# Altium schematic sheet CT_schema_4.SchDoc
size 193 x 163 mm
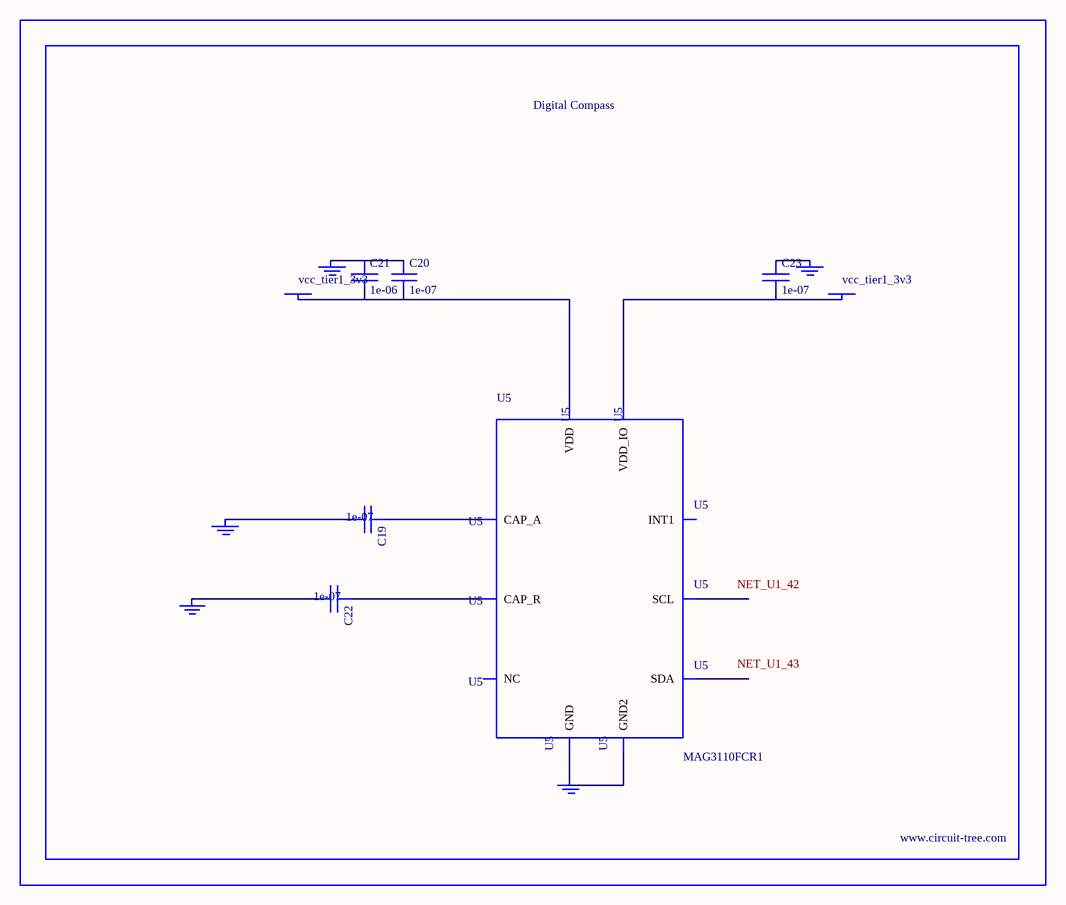
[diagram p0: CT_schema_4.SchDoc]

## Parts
BORDER3  (no value)
C19  1e-07  [C0402]
C20  1e-07  [C0402]
C21  1e-06  [C0603]
C22  1e-07  [C0402]
C23  1e-07  [C0402]
GND_INSTANCE_3_0  (no value)
GND_INSTANCE_3_1  (no value)
GND_INSTANCE_3_2  (no value)
GND_INSTANCE_3_3  (no value)
GND_INSTANCE_3_4  (no value)
POWER_INSTANCE_3_0  vcc_tier1_3v3
POWER_INSTANCE_3_1  vcc_tier1_3v3
U5  MAG3110FCR1  [DFN-10]

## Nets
NetC19_1: C19.1 U5.1(CAP_A)
NetC19_2: C19.2 GND_INSTANCE_3_0.0(GND)
NetC20_1: C20.1 C21.1 GND_INSTANCE_3_1.0(GND)
NetC20_2: C20.2 C21.2 POWER_INSTANCE_3_0.0(PWR) U5.2(VDD)
NetC22_1: C22.1 U5.4(CAP_R)
NetC22_2: C22.2 GND_INSTANCE_3_2.0(GND)
NetC23_1: C23.1 GND_INSTANCE_3_3.0(GND)
NetC23_2: C23.2 POWER_INSTANCE_3_1.0(PWR) U5.8(VDD_IO)
NetGND_INSTANCE_3_4_0: GND_INSTANCE_3_4.0(GND) U5.5(GND) U5.10(GND2)

Not connected (* = marked no-connect by the designer): U5 3(NC) 6(SDA) 7(SCL) 9(INT1)

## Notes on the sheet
- Labels drawn without touching a wire or pin: NET_U1_42, NET_U1_43

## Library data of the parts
BORDER3 = BORDER_PAGE3
C19 C20 C22 C23 = C0402C104K3RACTU
C21 = C0603C105K3RACTU
GND_INSTANCE_3_0-GND_INSTANCE_3_4 = GND
POWER_INSTANCE_3_0 POWER_INSTANCE_3_1 = PWR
